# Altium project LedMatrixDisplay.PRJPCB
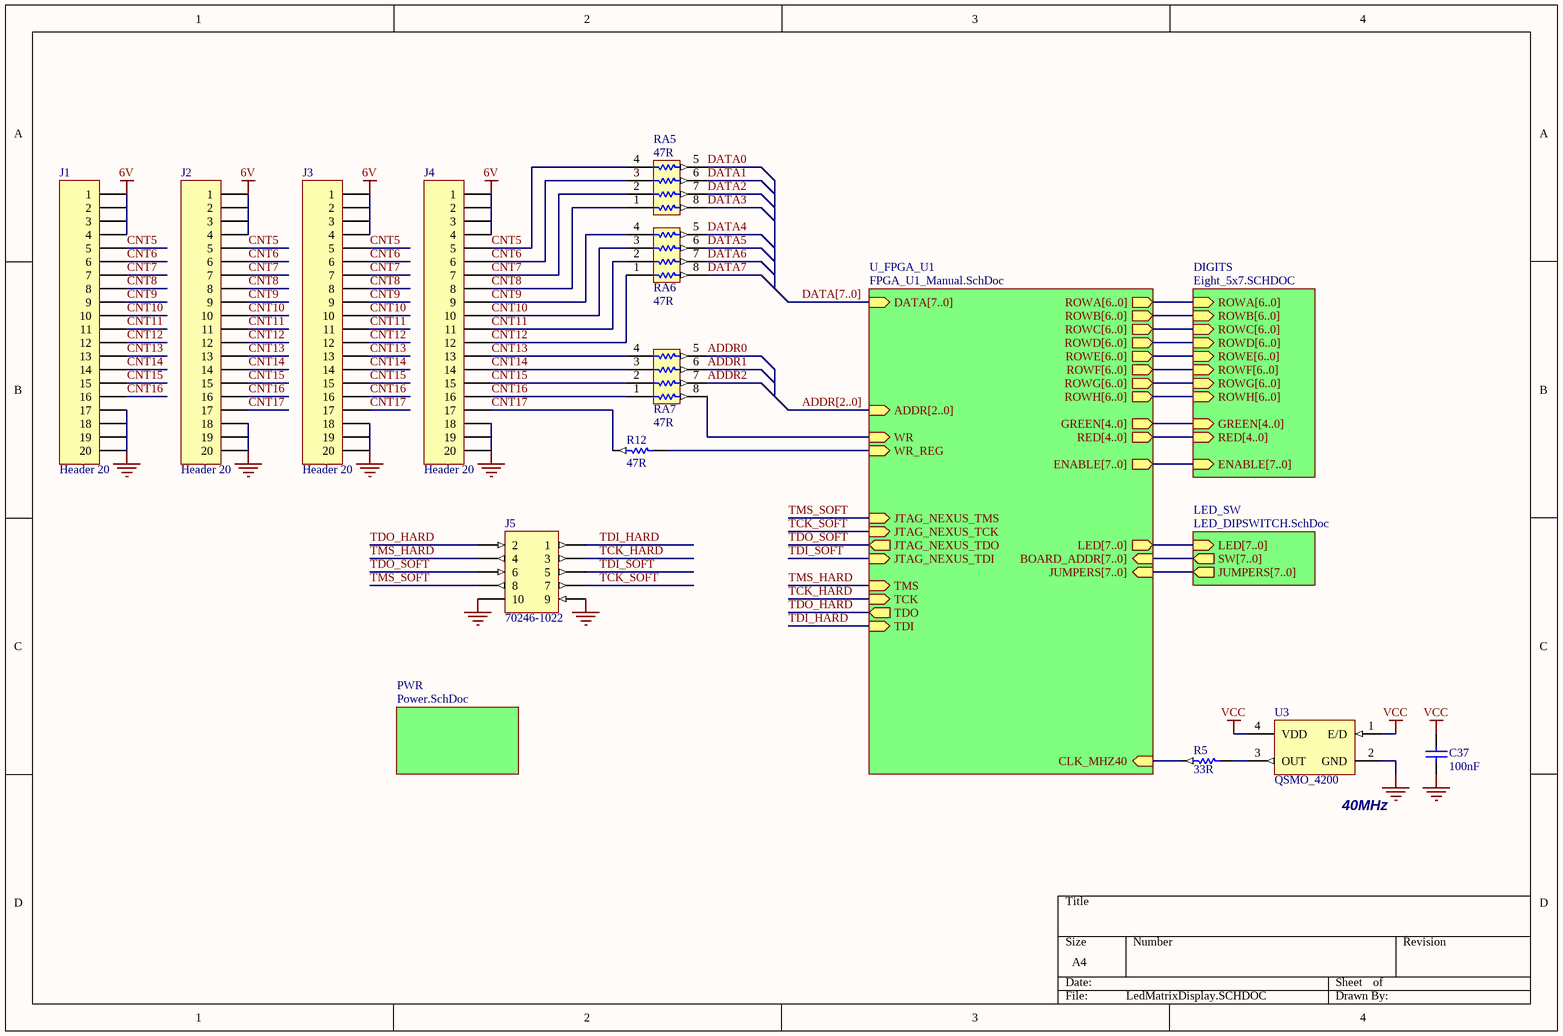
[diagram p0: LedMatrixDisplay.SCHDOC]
7 sheets, 103 parts. Net scope: hierarchical (ports join the sheet entries above them; power ports are global).
Board file: LedMatrixDisplay.PCBDOC
Sheets:
  LedMatrixDisplay.SCHDOC
    DIGITS = Eight_5x7.SCHDOC
      DG7 = DigitHolder.SCHDOC
      DG6 = DigitHolder.SCHDOC
      DG5 = DigitHolder.SCHDOC
      DG4 = DigitHolder.SCHDOC
      DG3 = DigitHolder.SCHDOC
      DG2 = DigitHolder.SCHDOC
      DG1 = DigitHolder.SCHDOC
      DG8 = DigitHolder.SCHDOC
    U_FPGA_U1 = FPGA_U1_Manual.SchDoc
      U_FPGA_U1_Auto = FPGA_U1_Auto.SchDoc
    PWR = Power.SchDoc
    LED_SW = LED_DIPSWITCH.SchDoc

## Sheet LedMatrixDisplay.SCHDOC
size A4; DocumentNumber: 1; SheetNumber: 1; SheetTotal: 7

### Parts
C37  100nF  [CC2012-0805]
J1  Header 20  [HDR2X10]
J2  Header 20  [HDR2X10]
J3  Header 20  [HDR2X10]
J4  Header 20  [HDR2X10]
J5  70246-1022  [HDR2X5_LP]
R5  33R  [CC2012-0805]
R12  47R  [CC2012-0805]
RA5  47R  [MNR34]
RA6  47R  [MNR34]
RA7  47R  [MNR34]
U3  QSMO_4200  [QSMO_4200]

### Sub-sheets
DIGITS = Eight_5x7.SCHDOC: ROWB[6..0] (in), ROWC[6..0] (in), ROWD[6..0] (in), ROWF[6..0] (in), ROWG[6..0] (in), ROWH[6..0] (in), ROWE[6..0] (in), ROWA[6..0] (in), GREEN[4..0] (in), RED[4..0] (in), ENABLE[7..0] (in)
LED_SW = LED_DIPSWITCH.SchDoc: LED[7..0] (in), SW[7..0] (out), JUMPERS[7..0] (out)
PWR = Power.SchDoc: no entries
U_FPGA_U1 = FPGA_U1_Manual.SchDoc: CLK_MHZ40 (in), DATA[7..0] (in), GREEN[4..0] (out), JTAG_NEXUS_TCK (in), JTAG_NEXUS_TDI (in), JTAG_NEXUS_TDO (out), JTAG_NEXUS_TMS (in), RED[4..0] (out), ADDR[2..0] (in), ROWA[6..0] (out), ROWB[6..0] (out), ROWC[6..0] (out), ROWD[6..0] (out), ROWE[6..0] (out), ROWF[6..0] (out), ROWG[6..0] (out), ROWH[6..0] (out), WR (in), TCK (in), TDI (in), TDO (out), TMS (in), BOARD_ADDR[7..0] (in), LED[7..0] (out), ENABLE[7..0] (out), JUMPERS[7..0] (in), WR_REG (in)

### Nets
6V: J1.1 J1.2 J1.3 J1.4 J2.1 J2.2 J2.3 J2.4 J3.1 J3.2 J3.3 J3.4 J4.1 J4.2 J4.3 J4.4
GND: C37.2 J1.17 J1.18 J1.19 J1.20 J2.18 J2.19 J2.20 J3.18 J3.19 J3.20 J4.18 J4.19 J4.20 J5.9 J5.10 U3.2(GND)
VCC: C37.1 U3.1(E/D) U3.4(VDD)  [project net VCCO]
ADDR0: RA7.5
ADDR1: RA7.6
ADDR2: RA7.7
CLK_MHZ40: R5.2 ; sheet U_FPGA_U1/CLK_MHZ40
CNT5: J1.5 J2.5 J3.5 J4.5 RA5.4
CNT6: J1.6 J2.6 J3.6 J4.6 RA5.3
CNT7: J1.7 J2.7 J3.7 J4.7 RA5.2
CNT8: J1.8 J2.8 J3.8 J4.8 RA5.1
CNT9: J1.9 J2.9 J3.9 J4.9 RA6.4
CNT10: J1.10 J2.10 J3.10 J4.10 RA6.3
CNT11: J1.11 J2.11 J3.11 J4.11 RA6.2
CNT12: J1.12 J2.12 J3.12 J4.12 RA6.1
CNT13: J1.13 J2.13 J3.13 J4.13 RA7.4
CNT14: J1.14 J2.14 J3.14 J4.14 RA7.3
CNT15: J1.15 J2.15 J3.15 J4.15 RA7.2
CNT16: J1.16 J2.16 J3.16 J4.16 RA7.1
CNT17: J2.17 J3.17 J4.17 R12.2
DATA0: RA5.5
DATA1: RA5.6
DATA2: RA5.7
DATA3: RA5.8
DATA4: RA6.5
DATA5: RA6.6
DATA6: RA6.7
DATA7: RA6.8
TCK_HARD: J5.3 ; sheet U_FPGA_U1/TCK
TCK_SOFT: J5.7 ; sheet U_FPGA_U1/JTAG_NEXUS_TCK
TDI_HARD: J5.1 ; sheet U_FPGA_U1/TDI
TDI_SOFT: J5.5 ; sheet U_FPGA_U1/JTAG_NEXUS_TDI
TDO_HARD: J5.2 ; sheet U_FPGA_U1/TDO
TDO_SOFT: J5.6 ; sheet U_FPGA_U1/JTAG_NEXUS_TDO
TMS_HARD: J5.4 ; sheet U_FPGA_U1/TMS
TMS_SOFT: J5.8 ; sheet U_FPGA_U1/JTAG_NEXUS_TMS
WR: RA7.8 ; sheet U_FPGA_U1/WR
WR_REG: R12.1 ; sheet U_FPGA_U1/WR_REG
NetR5_1: R5.1 U3.3(OUT)

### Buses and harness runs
bus ADDR[2..0] = sheet U_FPGA_U1/ADDR[2..0]
bus DATA[7..0] = sheet U_FPGA_U1/DATA[7..0]
bus sheet DIGITS/ENABLE[7..0] = sheet U_FPGA_U1/ENABLE[7..0]
bus sheet DIGITS/GREEN[4..0] = sheet U_FPGA_U1/GREEN[4..0]
bus sheet DIGITS/RED[4..0] = sheet U_FPGA_U1/RED[4..0]
bus sheet DIGITS/ROWA[6..0] = sheet U_FPGA_U1/ROWA[6..0]
bus sheet DIGITS/ROWB[6..0] = sheet U_FPGA_U1/ROWB[6..0]
bus sheet DIGITS/ROWC[6..0] = sheet U_FPGA_U1/ROWC[6..0]
bus sheet DIGITS/ROWD[6..0] = sheet U_FPGA_U1/ROWD[6..0]
bus sheet DIGITS/ROWE[6..0] = sheet U_FPGA_U1/ROWE[6..0]
bus sheet DIGITS/ROWF[6..0] = sheet U_FPGA_U1/ROWF[6..0]
bus sheet DIGITS/ROWG[6..0] = sheet U_FPGA_U1/ROWG[6..0]
bus sheet DIGITS/ROWH[6..0] = sheet U_FPGA_U1/ROWH[6..0]
bus sheet LED_SW/JUMPERS[7..0] = sheet U_FPGA_U1/JUMPERS[7..0]
bus sheet LED_SW/LED[7..0] = sheet U_FPGA_U1/LED[7..0]
bus sheet LED_SW/SW[7..0] = sheet U_FPGA_U1/BOARD_ADDR[7..0]

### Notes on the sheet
- (near U3) 40MHz

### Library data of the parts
C37 = CAP: Capacitor; Fitted: False
J1-J4 = Header 20: Header, 20-Pin; Manufacturer: Generic Components; Class I: Connector
J5 = Header 5X2: Header, 5-Pin, Dual row; Manufacturer: Molex; Class I: Connector; Fitted: True
R5 R12 = RES: Resistor; Fitted: False
RA5-RA7 = MNR34: 3216x4 Resistor Array; Fitted: True
U3 = QSMO_4200: Surface Mount Crystal Oscillator; Fitted: False

## Sheet Eight_5x7.SCHDOC
size A4 portrait; Organization: Altium Limited; Address1: L3, 12a Rodborough Rd; Address2: Frenchs Forest; Address3: NSW; Address4: Australia 2086; DocumentNumber: 2; SheetNumber: 2; SheetTotal: 7
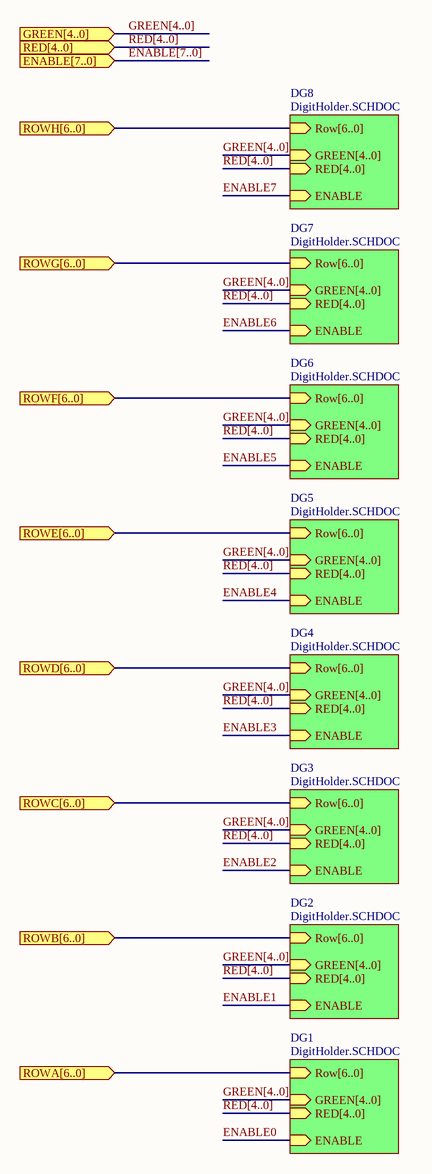
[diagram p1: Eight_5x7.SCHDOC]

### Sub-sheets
DG1 = DigitHolder.SCHDOC: Row[6..0] (in), ENABLE (in), GREEN[4..0] (in), RED[4..0] (in)
DG2 = DigitHolder.SCHDOC: Row[6..0] (in), ENABLE (in), GREEN[4..0] (in), RED[4..0] (in)
DG3 = DigitHolder.SCHDOC: Row[6..0] (in), ENABLE (in), GREEN[4..0] (in), RED[4..0] (in)
DG4 = DigitHolder.SCHDOC: Row[6..0] (in), ENABLE (in), GREEN[4..0] (in), RED[4..0] (in)
DG5 = DigitHolder.SCHDOC: Row[6..0] (in), ENABLE (in), GREEN[4..0] (in), RED[4..0] (in)
DG6 = DigitHolder.SCHDOC: Row[6..0] (in), ENABLE (in), GREEN[4..0] (in), RED[4..0] (in)
DG7 = DigitHolder.SCHDOC: Row[6..0] (in), ENABLE (in), GREEN[4..0] (in), RED[4..0] (in)
DG8 = DigitHolder.SCHDOC: Row[6..0] (in), ENABLE (in), GREEN[4..0] (in), RED[4..0] (in)

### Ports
ENABLE[7..0] (in), GREEN[4..0] (in), RED[4..0] (in), ROWA[6..0] (in), ROWB[6..0] (in), ROWC[6..0] (in), ROWD[6..0] (in), ROWE[6..0] (in), ROWF[6..0] (in), ROWG[6..0] (in), ROWH[6..0] (in)

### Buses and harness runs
bus ENABLE[7..0] = port ENABLE[7..0]
bus GREEN[4..0] = port GREEN[4..0]
bus GREEN[4..0] = sheet DG1/GREEN[4..0]
bus GREEN[4..0] = sheet DG2/GREEN[4..0]
bus GREEN[4..0] = sheet DG3/GREEN[4..0]
bus GREEN[4..0] = sheet DG4/GREEN[4..0]
bus GREEN[4..0] = sheet DG5/GREEN[4..0]
bus GREEN[4..0] = sheet DG6/GREEN[4..0]
bus GREEN[4..0] = sheet DG7/GREEN[4..0]
bus GREEN[4..0] = sheet DG8/GREEN[4..0]
bus port ROWA[6..0] = sheet DG1/Row[6..0]
bus port ROWB[6..0] = sheet DG2/Row[6..0]
bus port ROWC[6..0] = sheet DG3/Row[6..0]
bus port ROWD[6..0] = sheet DG4/Row[6..0]
bus port ROWE[6..0] = sheet DG5/Row[6..0]
bus port ROWF[6..0] = sheet DG6/Row[6..0]
bus port ROWG[6..0] = sheet DG7/Row[6..0]
bus port ROWH[6..0] = sheet DG8/Row[6..0]
bus RED[4..0] = port RED[4..0]
bus RED[4..0] = sheet DG1/RED[4..0]
bus RED[4..0] = sheet DG2/RED[4..0]
bus RED[4..0] = sheet DG3/RED[4..0]
bus RED[4..0] = sheet DG4/RED[4..0]
bus RED[4..0] = sheet DG5/RED[4..0]
bus RED[4..0] = sheet DG6/RED[4..0]
bus RED[4..0] = sheet DG7/RED[4..0]
bus RED[4..0] = sheet DG8/RED[4..0]

## Sheet DigitHolder.SCHDOC
size A4; DocumentNumber: 6; SheetNumber: 6; SheetTotal: 7
Used 8 times, as channels DIGITS/DG7, DIGITS/DG6, DIGITS/DG5, DIGITS/DG4, DIGITS/DG3, DIGITS/DG2, DIGITS/DG1, DIGITS/DG8. Parts and nets are listed once, with the designators drawn on the sheet.
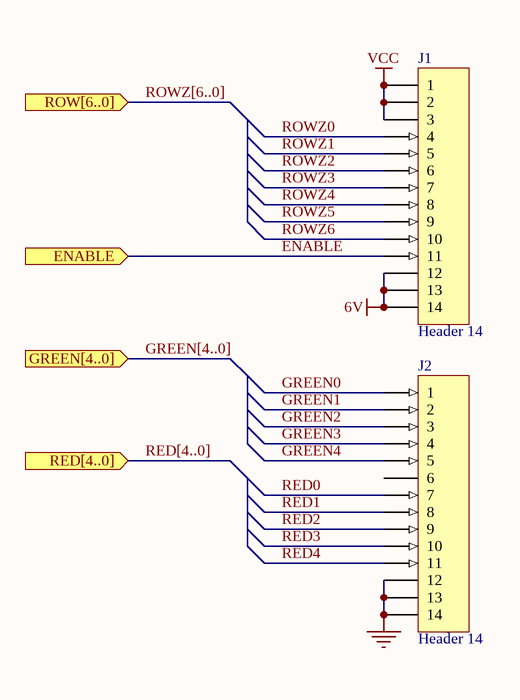
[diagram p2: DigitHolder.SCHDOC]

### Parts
J1  Header 14  [HDR1X14]
J2  Header 14  [HDR1X14]

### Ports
ENABLE (in), GREEN[4..0] (in), RED[4..0] (in), ROW[6..0] (in)

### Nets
6V: J1.12 J1.13 J1.14
GND: J2.12 J2.13 J2.14
VCC: J1.1 J1.2 J1.3
ENABLE: J1.11 ; port ENABLE
GREEN0: J2.1
GREEN1: J2.2
GREEN2: J2.3
GREEN3: J2.4
GREEN4: J2.5
RED0: J2.7
RED1: J2.8
RED2: J2.9
RED3: J2.10
RED4: J2.11
ROWZ0: J1.4
ROWZ1: J1.5
ROWZ2: J1.6
ROWZ3: J1.7
ROWZ4: J1.8
ROWZ5: J1.9
ROWZ6: J1.10

Not connected (* = marked no-connect by the designer): J2 6

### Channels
DIGITS/DG7: designators end in _DG7; ports ENABLE=ENABLE6
DIGITS/DG6: designators end in _DG6; ports ENABLE=ENABLE5
DIGITS/DG5: designators end in _DG5; ports ENABLE=ENABLE4
DIGITS/DG4: designators end in _DG4; ports ENABLE=ENABLE3
DIGITS/DG3: designators end in _DG3; ports ENABLE=ENABLE2
DIGITS/DG2: designators end in _DG2; ports ENABLE=ENABLE1
DIGITS/DG1: designators end in _DG1; ports ENABLE=ENABLE0
DIGITS/DG8: designators end in _DG8; ports ENABLE=ENABLE7

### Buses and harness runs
bus GREEN[4..0] = port GREEN[4..0]
bus RED[4..0] = port RED[4..0]
bus ROWZ[6..0] = port ROW[6..0]

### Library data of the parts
J1 J2 = Header 14: Header, 14-Pin; Manufacturer: Generic Components; Class I: Connector

## Sheet FPGA_U1_Manual.SchDoc
size A4; DocumentNumber: 4; SheetNumber: 4; SheetTotal: 7
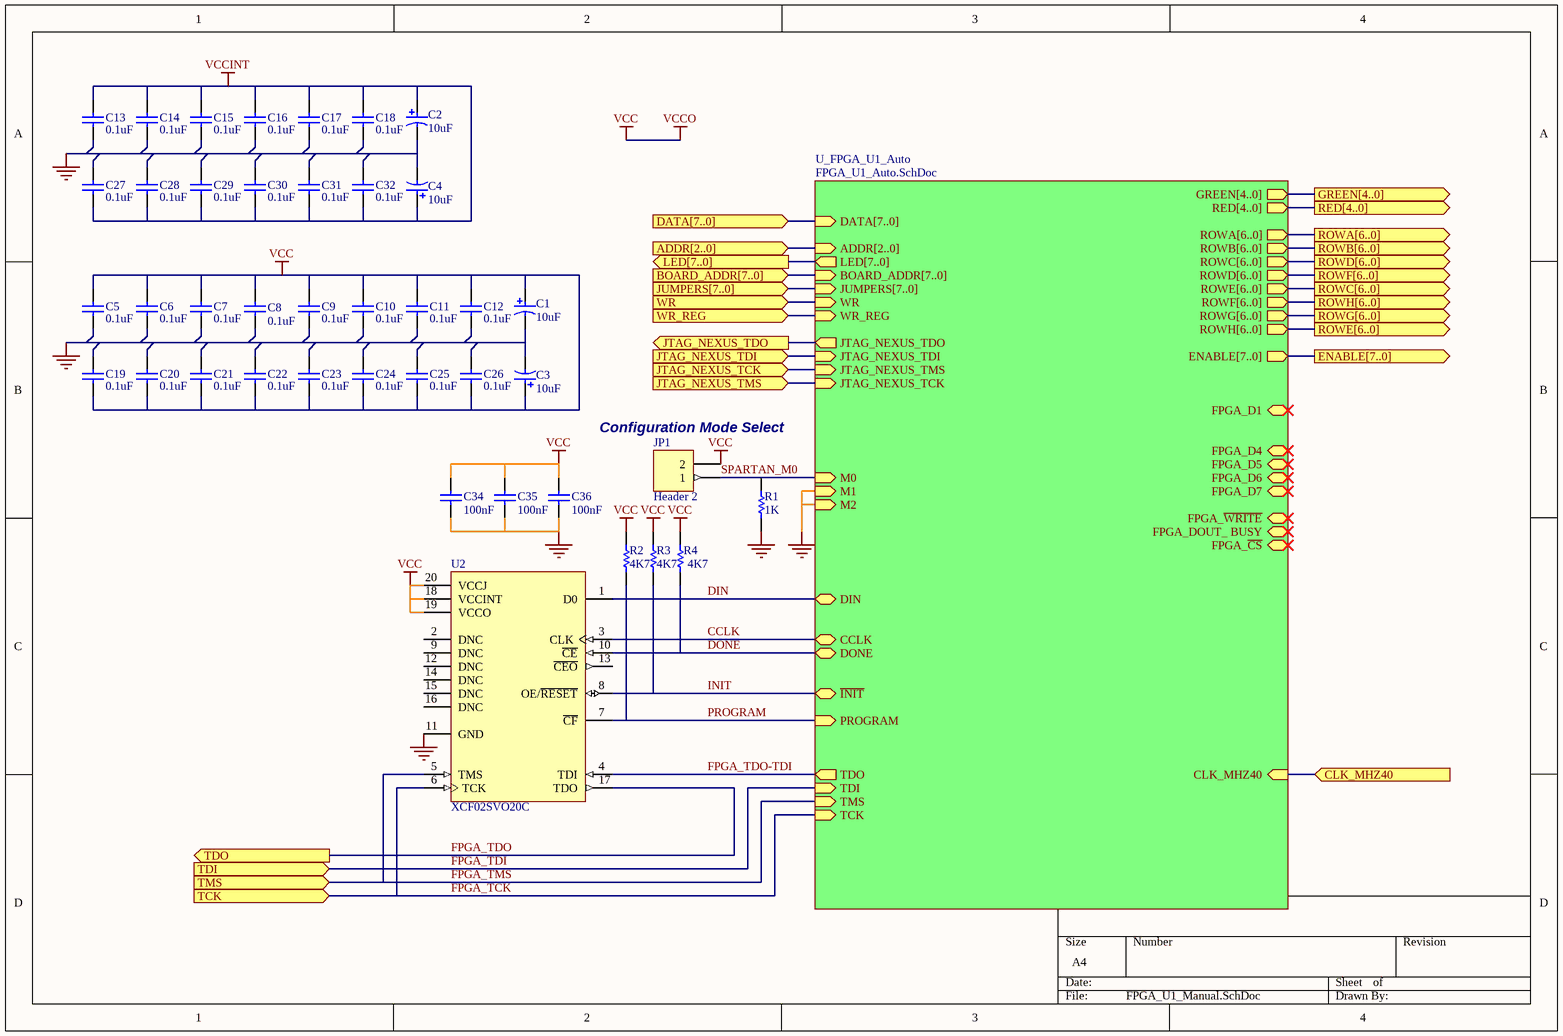
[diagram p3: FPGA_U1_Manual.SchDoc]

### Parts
C1  10uF  [MCCT-B]
C2  10uF  [MCCT-B]
C3  10uF  [MCCT-B]
C4  10uF  [MCCT-B]
C5  0.1uF  [CC2012-0805]
C6  0.1uF  [CC2012-0805]
C7  0.1uF  [CC2012-0805]
C8  0.1uF  [CC2012-0805]
C9  0.1uF  [CC2012-0805]
C10  0.1uF  [CC2012-0805]
C11  0.1uF  [CC2012-0805]
C12  0.1uF  [CC2012-0805]
C13  0.1uF  [CC2012-0805]
C14  0.1uF  [CC2012-0805]
C15  0.1uF  [CC2012-0805]
C16  0.1uF  [CC2012-0805]
C17  0.1uF  [CC2012-0805]
C18  0.1uF  [CC2012-0805]
C19  0.1uF  [CC2012-0805]
C20  0.1uF  [CC2012-0805]
C21  0.1uF  [CC2012-0805]
C22  0.1uF  [CC2012-0805]
C23  0.1uF  [CC2012-0805]
C24  0.1uF  [CC2012-0805]
C25  0.1uF  [CC2012-0805]
C26  0.1uF  [CC2012-0805]
C27  0.1uF  [CC2012-0805]
C28  0.1uF  [CC2012-0805]
C29  0.1uF  [CC2012-0805]
C30  0.1uF  [CC2012-0805]
C31  0.1uF  [CC2012-0805]
C32  0.1uF  [CC2012-0805]
C34  100nF  [CC2012-0805]
C35  100nF  [CC2012-0805]
C36  100nF  [CC2012-0805]
JP1  Header 2  Usage: Configuration Mode Select  [HDR1X2]
R1  1K  [CC2012-0805]
R2  4K7  [CC2012-0805]
R3  4K7  [CC2012-0805]
R4  4K7  [CC2012-0805]
U2  XCF02SVO20C  [VO20]

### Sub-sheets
U_FPGA_U1_Auto = FPGA_U1_Auto.SchDoc: ADDR[2..0] (in), BOARD_ADDR[7..0] (in), CLK_MHZ40 (in), DATA[7..0] (in), GREEN[4..0] (out), JTAG_NEXUS_TCK (in), JTAG_NEXUS_TDI (in), JTAG_NEXUS_TDO (out), JTAG_NEXUS_TMS (in), LED[7..0] (out), RED[4..0] (out), ROWA[6..0] (out), ROWB[6..0] (out), ROWC[6..0] (out), ROWD[6..0] (out), ROWE[6..0] (out), ROWF[6..0] (out), ROWG[6..0] (out), ROWH[6..0] (out), WR (in), CCLK (bidir), DONE (bidir), FPGA_D7 (bidir), M0 (in), M1 (in), M2 (in), PROGRAM (in), TCK (in), TDI (in), TDO (out), TMS (in), FPGA_DOUT_ BUSY (bidir), FPGA_~{WRITE} (bidir), FPGA_D5 (bidir), FPGA_D6 (bidir), FPGA_~{CS} (bidir), FPGA_D1 (bidir), FPGA_D4 (bidir), ENABLE[7..0] (out), JUMPERS[7..0] (in), DIN (bidir), ~{INIT} (bidir), WR_REG (in)

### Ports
ADDR[2..0] (in), BOARD_ADDR[7..0] (in), CLK_MHZ40 (in), DATA[7..0] (in), ENABLE[7..0] (out), GREEN[4..0] (out), JTAG_NEXUS_TCK (in), JTAG_NEXUS_TDI (in), JTAG_NEXUS_TDO (out), JTAG_NEXUS_TMS (in), JUMPERS[7..0] (in), LED[7..0] (out), RED[4..0] (out), ROWA[6..0] (out), ROWB[6..0] (out), ROWC[6..0] (out), ROWD[6..0] (out), ROWE[6..0] (out), ROWF[6..0] (out), ROWG[6..0] (out), ROWH[6..0] (out), TCK (in), TDI (in), TDO (out), TMS (in), WR (in), WR_REG (in)

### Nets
GND: C1.2 C2.2 C3.2 C4.2 C5.1 C6.1 C7.1 C8.1 C9.1 C10.1 C11.1 C12.1 C13.1 C14.1 C15.1 C16.1 C17.1 C18.1 C19.2 C20.2 C21.2 C22.2 C23.2 C24.2 C25.2 C26.2 C27.2 C28.2 C29.2 C30.2 C31.2 C32.2 C34.1 C35.1 C36.1 R1.1 U2.11(GND) ; sheet U_FPGA_U1_Auto/M1, sheet U_FPGA_U1_Auto/M2
VCCINT: C2.1 C4.1 C13.2 C14.2 C15.2 C16.2 C17.2 C18.2 C27.1 C28.1 C29.1 C30.1 C31.1 C32.1
VCCO: C1.1 C3.1 C5.2 C6.2 C7.2 C8.2 C9.2 C10.2 C11.2 C12.2 C19.1 C20.1 C21.1 C22.1 C23.1 C24.1 C25.1 C26.1 C34.2 C35.2 C36.2 JP1.2 R2.1 R3.1 R4.1 U2.18(VCCINT) U2.19(VCCO) U2.20(VCCJ)  [also labelled VCC]
CCLK: U2.3(CLK) ; sheet U_FPGA_U1_Auto/CCLK
CLK_MHZ40: port CLK_MHZ40, sheet U_FPGA_U1_Auto/CLK_MHZ40
DIN: U2.1(D0) ; sheet U_FPGA_U1_Auto/DIN
DONE: R4.2 U2.10(~{CE}) ; sheet U_FPGA_U1_Auto/DONE
FPGA_TCK: U2.6(TCK) ; port TCK, sheet U_FPGA_U1_Auto/TCK  [project net TCK_HARD]
FPGA_TDI: port TDI, sheet U_FPGA_U1_Auto/TDI  [project net TDI_HARD]
FPGA_TDO: U2.17(TDO) ; port TDO  [project net TDO_HARD]
FPGA_TDO-TDI: U2.4(TDI) ; sheet U_FPGA_U1_Auto/TDO
FPGA_TMS: U2.5(TMS) ; port TMS, sheet U_FPGA_U1_Auto/TMS  [project net TMS_HARD]
INIT: R3.2 U2.8(OE/~{RESET}) ; sheet U_FPGA_U1_Auto/~{INIT}
PROGRAM: R2.2 U2.7(~{CF}) ; sheet U_FPGA_U1_Auto/PROGRAM
SPARTAN_M0: JP1.1 R1.2 ; sheet U_FPGA_U1_Auto/M0
TCK_SOFT: port JTAG_NEXUS_TCK, sheet U_FPGA_U1_Auto/JTAG_NEXUS_TMS
TDI_SOFT: port JTAG_NEXUS_TDI, sheet U_FPGA_U1_Auto/JTAG_NEXUS_TDI
TDO_SOFT: port JTAG_NEXUS_TDO, sheet U_FPGA_U1_Auto/JTAG_NEXUS_TDO
TMS_SOFT: port JTAG_NEXUS_TMS, sheet U_FPGA_U1_Auto/JTAG_NEXUS_TCK
WR: port WR, sheet U_FPGA_U1_Auto/WR
WR_REG: port WR_REG, sheet U_FPGA_U1_Auto/WR_REG

Not connected (* = marked no-connect by the designer): U2 2(DNC) 9(DNC) 12(DNC) 13(~{CEO}) 14(DNC) 15(DNC) 16(DNC)

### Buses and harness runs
bus port ADDR[2..0] = sheet U_FPGA_U1_Auto/ADDR[2..0]
bus port BOARD_ADDR[7..0] = sheet U_FPGA_U1_Auto/BOARD_ADDR[7..0]
bus port DATA[7..0] = sheet U_FPGA_U1_Auto/DATA[7..0]
bus port ENABLE[7..0] = sheet U_FPGA_U1_Auto/ENABLE[7..0]
bus port GREEN[4..0] = sheet U_FPGA_U1_Auto/GREEN[4..0]
bus port JUMPERS[7..0] = sheet U_FPGA_U1_Auto/JUMPERS[7..0]
bus port LED[7..0] = sheet U_FPGA_U1_Auto/LED[7..0]
bus port RED[4..0] = sheet U_FPGA_U1_Auto/RED[4..0]
bus port ROWA[6..0] = sheet U_FPGA_U1_Auto/ROWA[6..0]
bus port ROWB[6..0] = sheet U_FPGA_U1_Auto/ROWB[6..0]
bus port ROWC[6..0] = sheet U_FPGA_U1_Auto/ROWE[6..0]
bus port ROWD[6..0] = sheet U_FPGA_U1_Auto/ROWC[6..0]
bus port ROWE[6..0] = sheet U_FPGA_U1_Auto/ROWH[6..0]
bus port ROWF[6..0] = sheet U_FPGA_U1_Auto/ROWD[6..0]
bus port ROWG[6..0] = sheet U_FPGA_U1_Auto/ROWG[6..0]
bus port ROWH[6..0] = sheet U_FPGA_U1_Auto/ROWF[6..0]

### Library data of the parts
C1-C4 = CAP_POLAR: Polar Capacitor
C5-C32 = CAP: Capacitor
C34-C36 = CAP: Capacitor; Fitted: True
JP1 = Header 2: Header, 2-Pin; Manufacturer: Generic Components; Class I: Connector; Fitted: True
R1-R4 = RES: Resistor; Fitted: True
U2 = XCF02SVO20C: XCF00S Series, Platform Flash In-System Programmable Configuration 3.3V PROM, 20-Pin TSOP, 2-Megabit, Commercial Grade; Manufacturer: Xilinx; Package Information: Latest Revision: ver1.0, May-2003; Code - JEDEC: MO-153-AC

## Sheet FPGA_U1_Auto.SchDoc
size A2; DocumentNumber: 7; SheetNumber: 7; SheetTotal: 7; Generated From FPGA Project: LedMatrix.PrjFpg; UNUSED_SPECIAL: RouteSeparate; UNUSED_IO: NoERC; VREF: NoERC; UNUSED_INPUT: NoERC
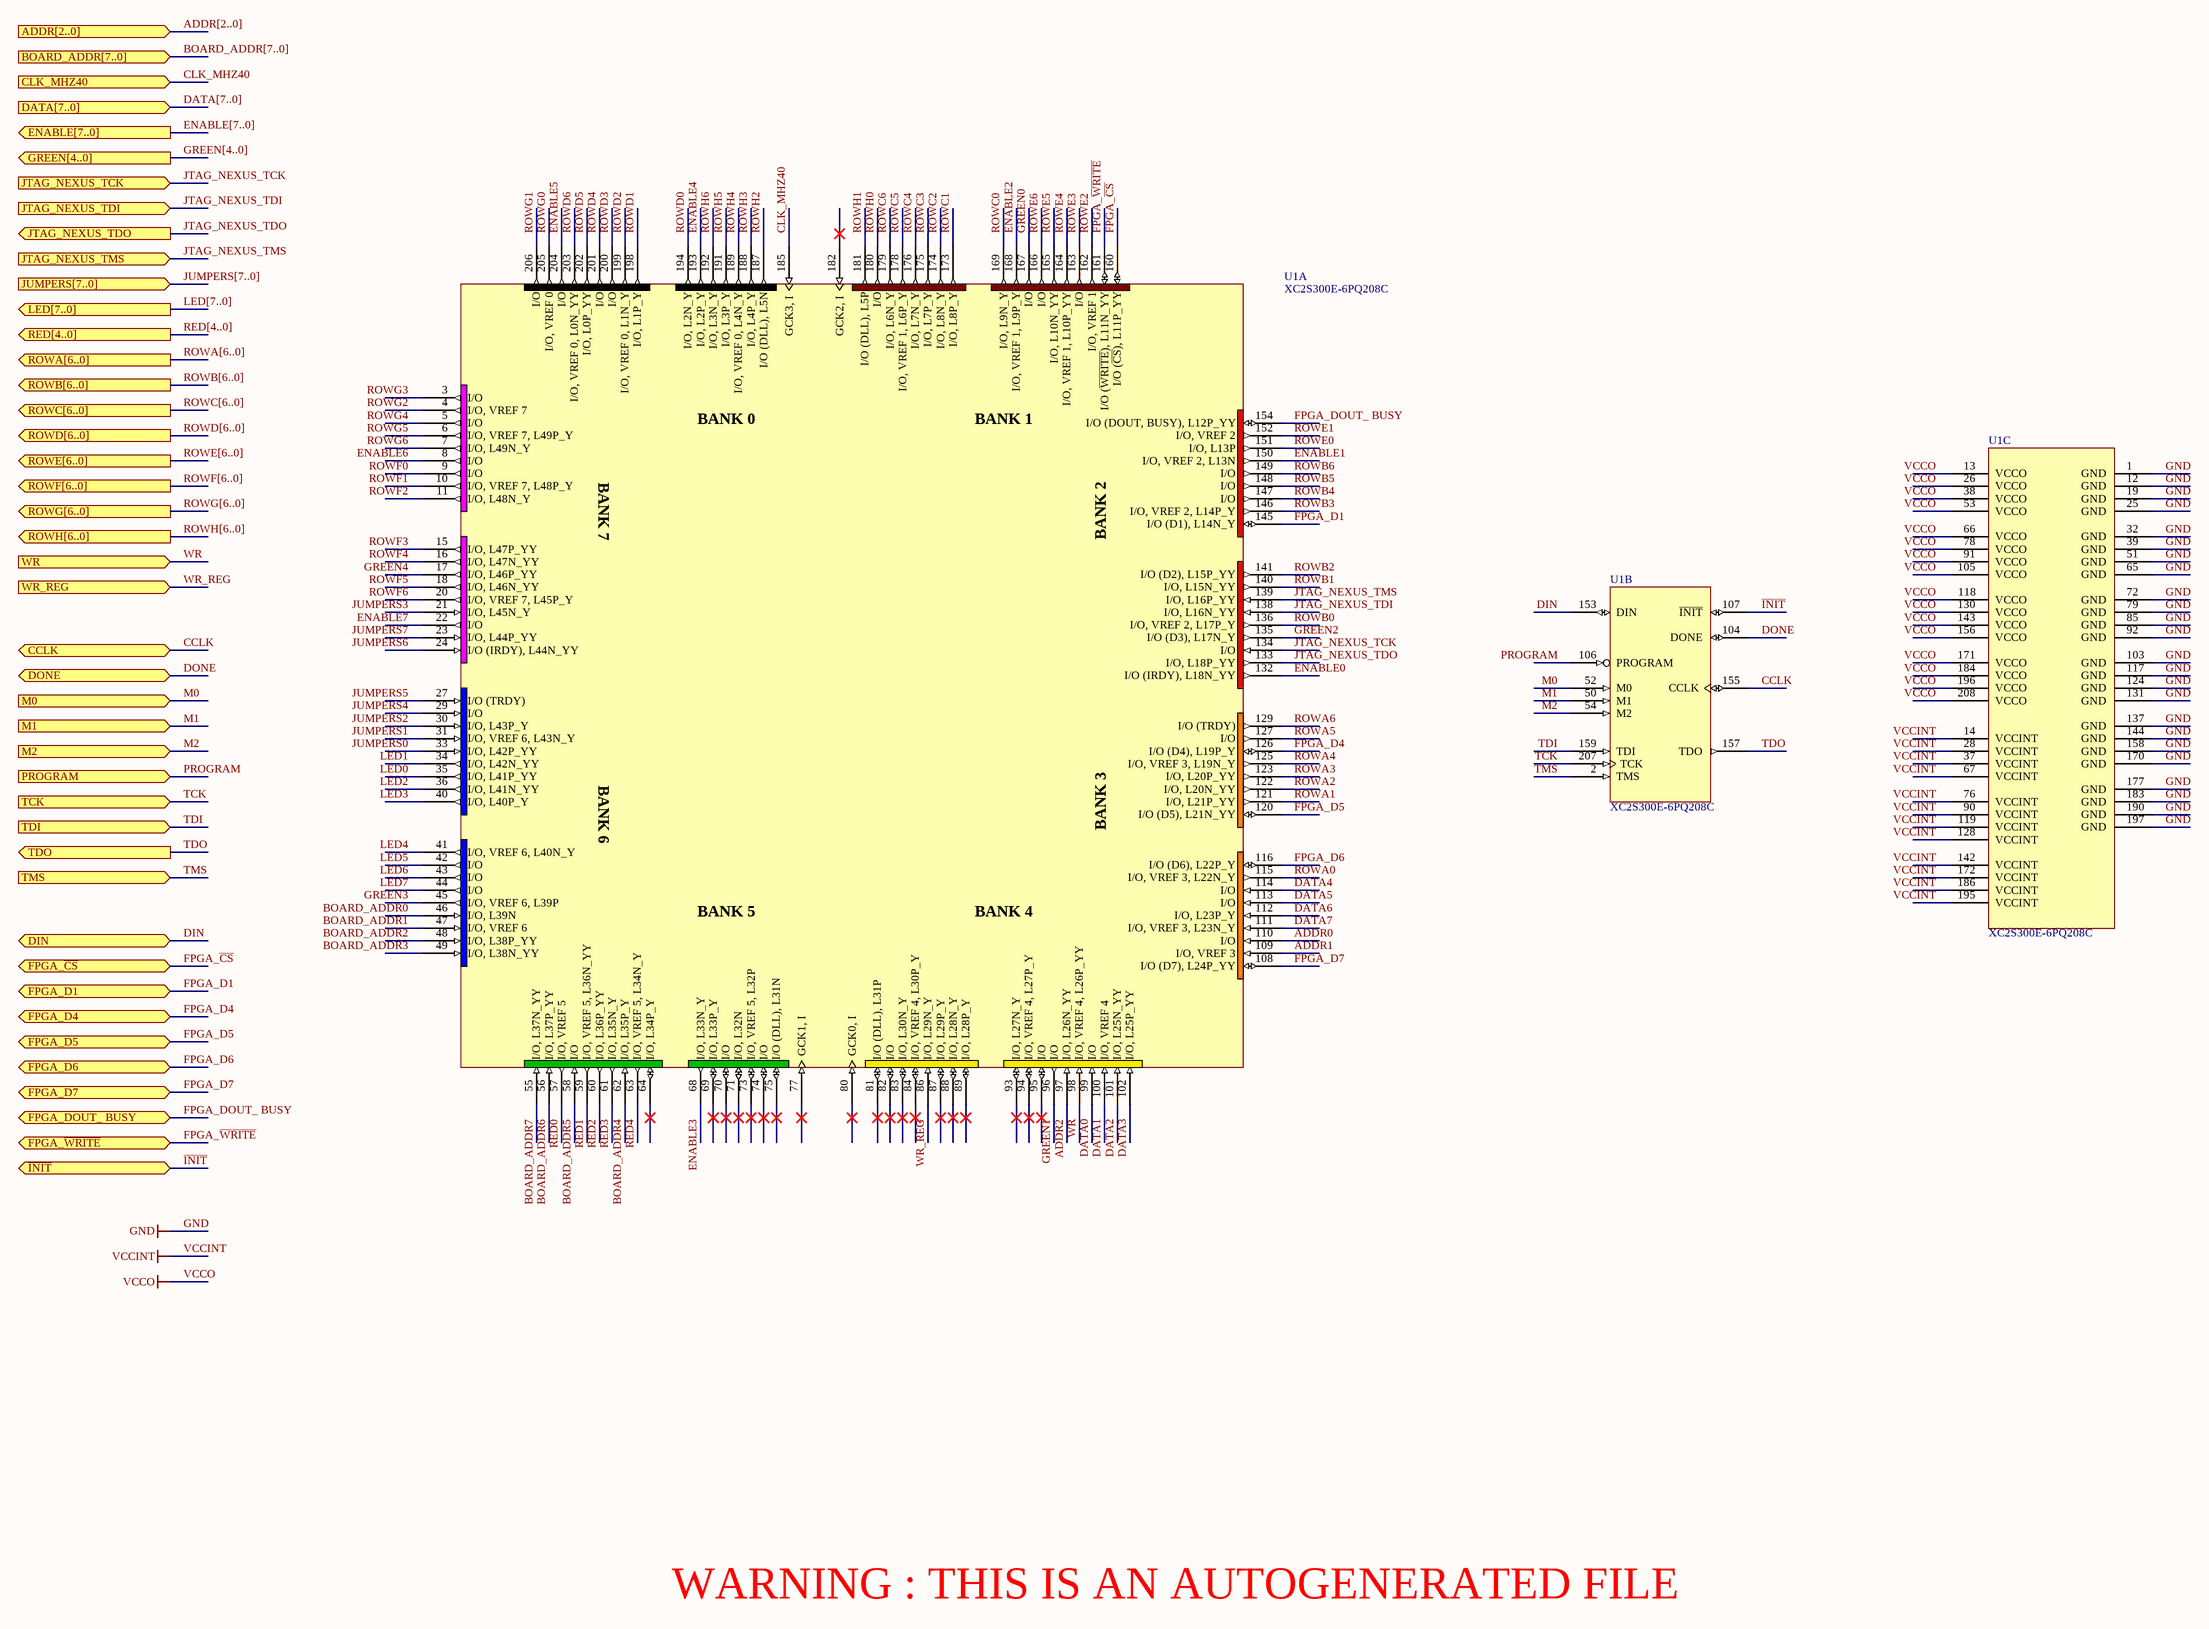
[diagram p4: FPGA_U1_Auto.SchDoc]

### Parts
U1  XC2S300E-6PQ208C  [PQ208]  (parts A,B,C of 3)

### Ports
ADDR[2..0] (in), BOARD_ADDR[7..0] (in), CCLK (bidir), CLK_MHZ40 (in), DATA[7..0] (in), DIN (bidir), DONE (bidir), ENABLE[7..0] (out), FPGA_D1 (bidir), FPGA_D4 (bidir), FPGA_D5 (bidir), FPGA_D6 (bidir), FPGA_D7 (bidir), FPGA_DOUT_ BUSY (bidir), FPGA_~{CS} (bidir), FPGA_~{WRITE} (bidir), GREEN[4..0] (out), JTAG_NEXUS_TCK (in), JTAG_NEXUS_TDI (in), JTAG_NEXUS_TDO (out), JTAG_NEXUS_TMS (in), JUMPERS[7..0] (in), LED[7..0] (out), M0 (in), M1 (in), M2 (in), PROGRAM (in), RED[4..0] (out), ROWA[6..0] (out), ROWB[6..0] (out), ROWC[6..0] (out), ROWD[6..0] (out), ROWE[6..0] (out), ROWF[6..0] (out), ROWG[6..0] (out), ROWH[6..0] (out), TCK (in), TDI (in), TDO (out), TMS (in), WR (in), WR_REG (in), ~{INIT} (bidir)

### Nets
GND: U1.1(GND) U1.12(GND) U1.19(GND) U1.25(GND) U1.32(GND) U1.39(GND) U1.50(M1) U1.51(GND) U1.54(M2) U1.65(GND) U1.72(GND) U1.79(GND) U1.85(GND) U1.92(GND) U1.103(GND) U1.117(GND) U1.124(GND) U1.131(GND) U1.137(GND) U1.144(GND) U1.158(GND) U1.170(GND) U1.177(GND) U1.183(GND) U1.190(GND) U1.197(GND) ; port M1, port M2  [also labelled M1, M2]
VCCINT: U1.14(VCCINT) U1.28(VCCINT) U1.37(VCCINT) U1.67(VCCINT) U1.76(VCCINT) U1.90(VCCINT) U1.119(VCCINT) U1.128(VCCINT) U1.142(VCCINT) U1.172(VCCINT) U1.186(VCCINT) U1.195(VCCINT)
VCCO: U1.13(VCCO) U1.26(VCCO) U1.38(VCCO) U1.53(VCCO) U1.66(VCCO) U1.78(VCCO) U1.91(VCCO) U1.105(VCCO) U1.118(VCCO) U1.130(VCCO) U1.143(VCCO) U1.156(VCCO) U1.171(VCCO) U1.184(VCCO) U1.196(VCCO) U1.208(VCCO)
ADDR0: U1.110(I/O)
ADDR1: U1.109(I/O,_VREF_3)
ADDR2: U1.97(I/O,_L26N_YY)
BOARD_ADDR0: U1.46(I/O,_L39N)  [project net SW0]
BOARD_ADDR1: U1.47(I/O,_VREF_6)  [project net SW1]
BOARD_ADDR2: U1.48(I/O,_L38P_YY)  [project net SW2]
BOARD_ADDR3: U1.49(I/O,_L38N_YY)  [project net SW3]
BOARD_ADDR4: U1.62(I/O,_L35P_Y)  [project net SW4]
BOARD_ADDR5: U1.58(I/O)  [project net SW5]
BOARD_ADDR6: U1.56(I/O,_L37P_YY)  [project net SW6]
BOARD_ADDR7: U1.55(I/O,_L37N_YY)  [project net SW7]
CCLK: U1.155(CCLK) ; port CCLK
CLK_MHZ40: U1.185(GCK3,_I) ; port CLK_MHZ40
DATA0: U1.99(I/O)
DATA1: U1.100(I/O,_VREF_4)
DATA2: U1.101(I/O,_L25N_YY)
DATA3: U1.102(I/O,_L25P_YY)
DATA4: U1.114(I/O)
DATA5: U1.113(I/O)
DATA6: U1.112(I/O,_L23P_Y)
DATA7: U1.111(I/O,_VREF_3,_L23N_Y)
DIN: U1.153(DIN) ; port DIN
DONE: U1.104(DONE) ; port DONE
ENABLE0: U1.132(I/O_(IRDY),_L18N_YY)
ENABLE1: U1.150(I/O,_VREF_2,_L13N)
ENABLE2: U1.168(I/O,_VREF_1,_L9P_Y)
ENABLE3: U1.68(I/O,_L33N_Y)
ENABLE4: U1.193(I/O,_L2P_Y)
ENABLE5: U1.204(I/O)
ENABLE6: U1.8(I/O)
ENABLE7: U1.22(I/O)
FPGA_~{CS}: U1.160(I/O_(~{CS}),_L11P_YY) ; port FPGA_~{CS}
FPGA_D1: U1.145(I/O_(D1),_L14N_Y) ; port FPGA_D1
FPGA_D4: U1.126(I/O_(D4),_L19P_Y) ; port FPGA_D4
FPGA_D5: U1.120(I/O_(D5),_L21N_YY) ; port FPGA_D5
FPGA_D6: U1.116(I/O_(D6),_L22P_Y) ; port FPGA_D6
FPGA_D7: U1.108(I/O_(D7),_L24P_YY) ; port FPGA_D7
FPGA_DOUT_ BUSY: U1.154(I/O_(DOUT,_BUSY),_L12P_YY) ; port FPGA_DOUT_ BUSY
FPGA_~{WRITE}: U1.161(I/O_(~{WRITE}),_L11N_YY) ; port FPGA_~{WRITE}
GREEN0: U1.167(I/O)
GREEN1: U1.96(I/O)
GREEN2: U1.135(I/O_(D3),_L17N_Y)
GREEN3: U1.45(I/O,_VREF_6,_L39P)
GREEN4: U1.17(I/O,_L46P_YY)
~{INIT}: U1.107(~{INIT}) ; port ~{INIT}  [project net INIT]
JTAG_NEXUS_TCK: U1.134(I/O) ; port JTAG_NEXUS_TCK  [project net TMS_SOFT]
JTAG_NEXUS_TDI: U1.138(I/O,_L16N_YY) ; port JTAG_NEXUS_TDI  [project net TDI_SOFT]
JTAG_NEXUS_TDO: U1.133(I/O,_L18P_YY) ; port JTAG_NEXUS_TDO  [project net TDO_SOFT]
JTAG_NEXUS_TMS: U1.139(I/O,_L16P_YY) ; port JTAG_NEXUS_TMS  [project net TCK_SOFT]
JUMPERS0: U1.33(I/O,_L42P_YY)
JUMPERS1: U1.31(I/O,_VREF_6,_L43N_Y)
JUMPERS2: U1.30(I/O,_L43P_Y)
JUMPERS3: U1.21(I/O,_L45N_Y)
JUMPERS4: U1.29(I/O)
JUMPERS5: U1.27(I/O_(TRDY))
JUMPERS6: U1.24(I/O_(IRDY),_L44N_YY)
JUMPERS7: U1.23(I/O,_L44P_YY)
LED0: U1.35(I/O,_L41P_YY)
LED1: U1.34(I/O,_L42N_YY)
LED2: U1.36(I/O,_L41N_YY)
LED3: U1.40(I/O,_L40P_Y)
LED4: U1.41(I/O,_VREF_6,_L40N_Y)
LED5: U1.42(I/O)
LED6: U1.43(I/O)
LED7: U1.44(I/O)
M0: U1.52(M0) ; port M0  [project net SPARTAN_M0]
PROGRAM: U1.106(PROGRAM) ; port PROGRAM
RED0: U1.57(I/O,_VREF_5)
RED1: U1.59(I/O,_VREF_5,_L36N_YY)
RED2: U1.60(I/O,_L36P_YY)
RED3: U1.61(I/O,_L35N_Y)
RED4: U1.63(I/O,_VREF_5,_L34N_Y)
ROWA0: U1.115(I/O,_VREF_3,_L22N_Y)
ROWA1: U1.121(I/O,_L21P_YY)
ROWA2: U1.122(I/O,_L20N_YY)
ROWA3: U1.123(I/O,_L20P_YY)
ROWA4: U1.125(I/O,_VREF_3,_L19N_Y)
ROWA5: U1.127(I/O)
ROWA6: U1.129(I/O_(TRDY))
ROWB0: U1.136(I/O,_VREF_2,_L17P_Y)
ROWB1: U1.140(I/O,_L15N_YY)
ROWB2: U1.141(I/O_(D2),_L15P_YY)
ROWB3: U1.146(I/O,_VREF_2,_L14P_Y)
ROWB4: U1.147(I/O)
ROWB5: U1.148(I/O)
ROWB6: U1.149(I/O)
ROWC0: U1.169(I/O,_L9N_Y)
ROWC1: U1.173(I/O,_L8P_Y)
ROWC2: U1.174(I/O,_L8N_Y)
ROWC3: U1.175(I/O,_L7P_Y)
ROWC4: U1.176(I/O,_L7N_Y)
ROWC5: U1.178(I/O,_VREF_1,_L6P_Y)
ROWC6: U1.179(I/O,_L6N_Y)
ROWD0: U1.194(I/O,_L2N_Y)
ROWD1: U1.198(I/O,_L1P_Y)
ROWD2: U1.199(I/O,_VREF_0,_L1N_Y)
ROWD3: U1.200(I/O)
ROWD4: U1.201(I/O)
ROWD5: U1.202(I/O,_L0P_YY)
ROWD6: U1.203(I/O,_VREF_0,_L0N_YY)
ROWE0: U1.151(I/O,_L13P)
ROWE1: U1.152(I/O,_VREF_2)
ROWE2: U1.162(I/O,_VREF_1)
ROWE3: U1.163(I/O)
ROWE4: U1.164(I/O,_VREF_1,_L10P_YY)
ROWE5: U1.165(I/O,_L10N_YY)
ROWE6: U1.166(I/O)
ROWF0: U1.9(I/O)
ROWF1: U1.10(I/O,_VREF_7,_L48P_Y)
ROWF2: U1.11(I/O,_L48N_Y)
ROWF3: U1.15(I/O,_L47P_YY)
ROWF4: U1.16(I/O,_L47N_YY)
ROWF5: U1.18(I/O,_L46N_YY)
ROWF6: U1.20(I/O,_VREF_7,_L45P_Y)
ROWG0: U1.205(I/O,_VREF_0)
ROWG1: U1.206(I/O)
ROWG2: U1.4(I/O,_VREF_7)
ROWG3: U1.3(I/O)
ROWG4: U1.5(I/O)
ROWG5: U1.6(I/O,_VREF_7,_L49P_Y)
ROWG6: U1.7(I/O,_L49N_Y)
ROWH0: U1.180(I/O)
ROWH1: U1.181(I/O_(DLL),_L5P)
ROWH2: U1.187(I/O_(DLL),_L5N)
ROWH3: U1.188(I/O,_L4P_Y)
ROWH4: U1.189(I/O,_VREF_0,_L4N_Y)
ROWH5: U1.191(I/O,_L3P_Y)
ROWH6: U1.192(I/O,_L3N_Y)
TCK: U1.207(TCK) ; port TCK  [project net TCK_HARD]
TDI: U1.159(TDI) ; port TDI  [project net TDI_HARD]
TDO: U1.157(TDO) ; port TDO  [project net FPGA_TDO-TDI]
TMS: U1.2(TMS) ; port TMS  [project net TMS_HARD]
WR: U1.98(I/O,_VREF_4,_L26P_YY) ; port WR
WR_REG: U1.86(I/O,_L29N_Y) ; port WR_REG

Not connected (* = marked no-connect by the designer): U1 64(I/O,_L34P_Y)* 69(I/O,_L33P_Y)* 70(I/O)* 71(I/O,_L32N)* 73(I/O,_VREF_5,_L32P)* 74(I/O)* 75(I/O_(DLL),_L31N)* 77(GCK1,_I)* 80(GCK0,_I)* 81(I/O_(DLL),_L31P)* 82(I/O)* 83(I/O,_L30N_Y)* 84(I/O,_VREF_4,_L30P_Y)* 87(I/O,_L29P_Y)* 88(I/O,_L28N_Y)* 89(I/O,_L28P_Y)* 93(I/O,_L27N_Y)* 94(I/O,_VREF_4,_L27P_Y)* 95(I/O)* 182(GCK2,_I)*

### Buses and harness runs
bus ADDR[2..0] = port ADDR[2..0]
bus BOARD_ADDR[7..0] = port BOARD_ADDR[7..0]
bus DATA[7..0] = port DATA[7..0]
bus ENABLE[7..0] = port ENABLE[7..0]
bus GREEN[4..0] = port GREEN[4..0]
bus JUMPERS[7..0] = port JUMPERS[7..0]
bus LED[7..0] = port LED[7..0]
bus RED[4..0] = port RED[4..0]
bus ROWA[6..0] = port ROWA[6..0]
bus ROWB[6..0] = port ROWB[6..0]
bus ROWC[6..0] = port ROWC[6..0]
bus ROWD[6..0] = port ROWD[6..0]
bus ROWE[6..0] = port ROWE[6..0]
bus ROWF[6..0] = port ROWF[6..0]
bus ROWG[6..0] = port ROWG[6..0]
bus ROWH[6..0] = port ROWH[6..0]

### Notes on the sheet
- WARNING : THIS IS AN AUTOGENERATED FILE

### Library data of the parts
U1 = XC2S300E-6PQ208C: Spartan-IIE 1.8V FPGA, 208-Pin PQFP, Standard Performance, Commercial Grade; Package Information: Latest Revision: ver1.1, Oct-2002; Code - JEDEC: MS-029-FA-1

## Sheet Power.SchDoc: Board-On-Chip Power Supply
size A4; Organization: Altium Limited; Address1: L3, 12a Rodborough Rd; Address2: Frenchs Forest; Address3: NSW; Address4: Australia 2086; DocumentNumber: 3; Revision: 1.05; SheetNumber: 3; SheetTotal: 7
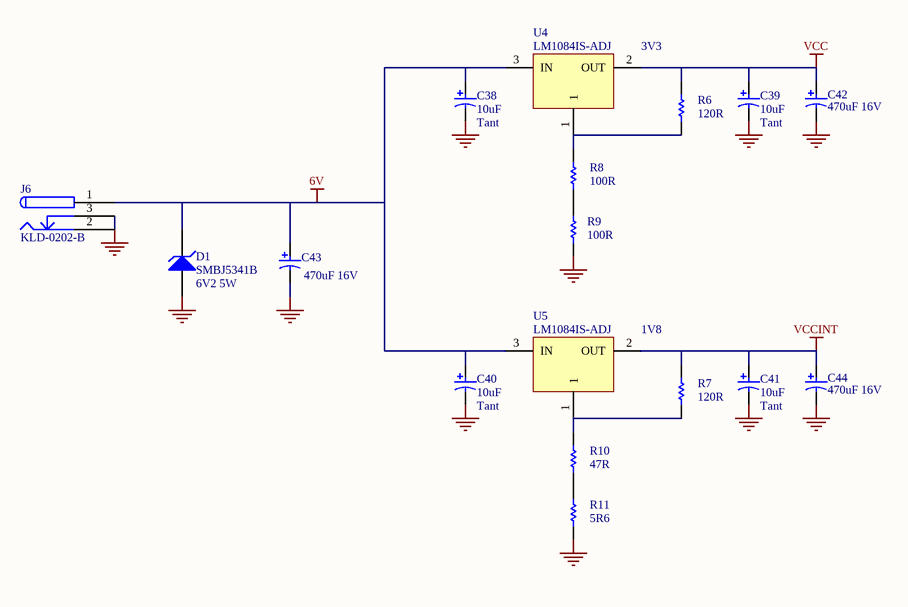
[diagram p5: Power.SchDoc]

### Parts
C38  10uF  Capacitor Type: Tant  [MCCT-B]
C39  10uF  Capacitor Type: Tant  [MCCT-B]
C40  10uF  Capacitor Type: Tant  [MCCT-B]
C41  10uF  Capacitor Type: Tant  [MCCT-B]
C42  470uF 16V  [RB8/3.5]
C43  470uF 16V  [RB8/3.5]
C44  470uF 16V  [RB8/3.5]
D1  SMBJ5341B  Part Description: 6V2 5W  [DO214]
J6  KLD-0202-B  [KLD-0202]
R6  120R  [CC2012-0805]
R7  120R  [CC2012-0805]
R8  100R  [CC2012-0805]
R9  100R  [CC2012-0805]
R10  47R  [CC2012-0805]
R11  5R6  [CC2012-0805]
U4  LM1084IS-ADJ  [TO-263]
U5  LM1084IS-ADJ  [TO-263]

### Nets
6V: C38.1 C40.1 C43.1 D1.2(K) J6.1 J6.1A J6.1B U4.3(IN) U5.3(IN)
GND: C38.2 C39.2 C40.2 C41.2 C42.2 C43.2 C44.2 D1.1(A) J6.2 J6.2A J6.2B J6.3 J6.3A J6.3B R9.1 R11.2
VCC: C39.1 C42.1 R6.1 U4.2(OUT)  [project net VCCO]
VCCINT: C41.1 C44.1 R7.1 U5.2(OUT)
NetR6_2: R6.2 R8.1 U4.1
NetR7_2: R7.2 R10.1 U5.1
NetR8_2: R8.2 R9.2
NetR10_2: R10.2 R11.1

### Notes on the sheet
- 3V3
- 1V8

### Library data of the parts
C38-C44 = CAP_POLAR: Polar Capacitor; Fitted: True
D1 = BZG03C13: Zener Diode, 6.2V, 5W; Manufacturer: Microsemi; Fitted: True
J6 = KLD-0202-B: Low Voltage Power Supply Connector; Manufacturer: Kycon; Fitted: True
R6-R11 = RES: Resistor; Fitted: True
U4 U5 = LM1084IS-ADJ: 5A Low Dropout Possitive Regulators; Fitted: True

## Sheet LED_DIPSWITCH.SchDoc: Board-On-Chip LEDs and DIP Switch
size A4; Organization: Altium Limited; Address1: L3, 12a Rodborough Rd; Address2: Frenchs Forest; Address3: NSW; Address4: Australia 2086; DocumentNumber: 5; Revision: 1.05; SheetNumber: 5; SheetTotal: 7
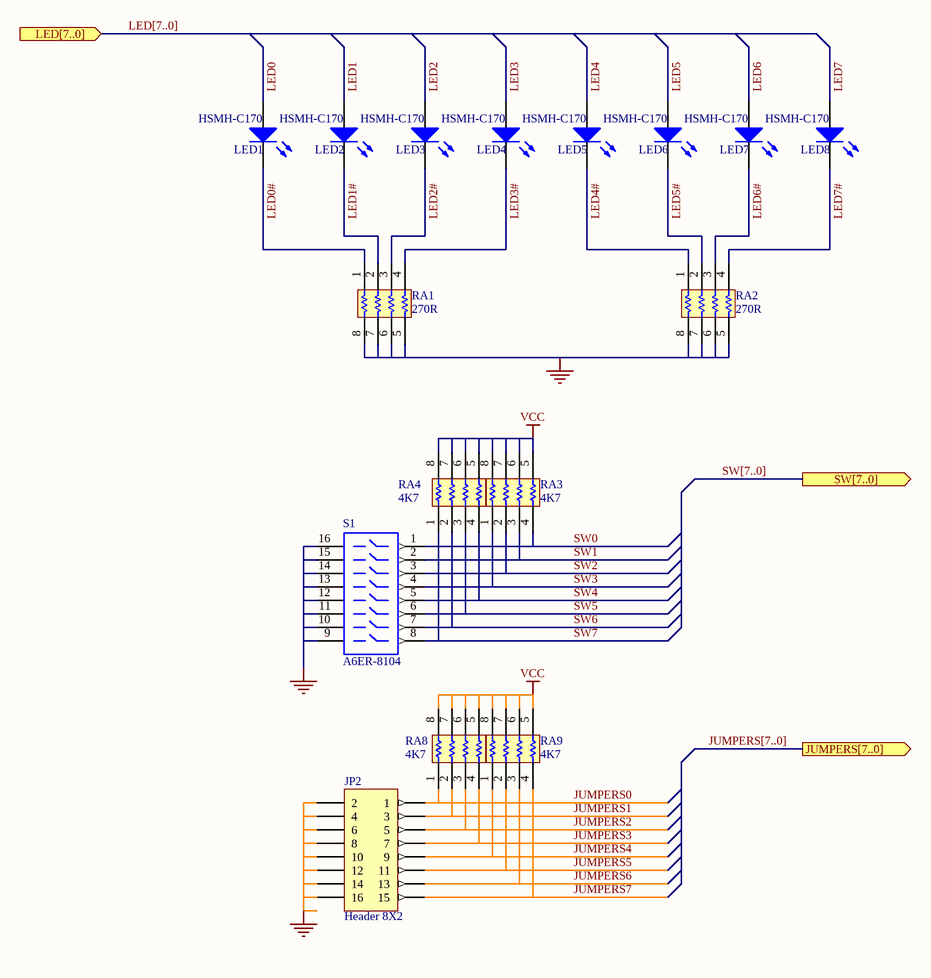
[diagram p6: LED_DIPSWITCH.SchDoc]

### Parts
JP2  Header 8X2  [HDR2X8]
LED1  HSMH-C170  [SMD _LED]
LED2  HSMH-C170  [SMD _LED]
LED3  HSMH-C170  [SMD _LED]
LED4  HSMH-C170  [SMD _LED]
LED5  HSMH-C170  [SMD _LED]
LED6  HSMH-C170  [SMD _LED]
LED7  HSMH-C170  [SMD _LED]
LED8  HSMH-C170  [SMD _LED]
RA1  270R  [MNR34]
RA2  270R  [MNR34]
RA3  4K7  [MNR34]
RA4  4K7  [MNR34]
RA8  4K7  [MNR34]
RA9  4K7  [MNR34]
S1  A6ER-8104  [DIP-16-KEY]

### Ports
JUMPERS[7..0] (out), LED[7..0] (in), SW[7..0] (out)

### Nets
GND: JP2.2 JP2.4 JP2.6 JP2.8 JP2.10 JP2.12 JP2.14 JP2.16 RA1.5 RA1.6 RA1.7 RA1.8 RA2.5 RA2.6 RA2.7 RA2.8 S1.9 S1.10 S1.11 S1.12 S1.13 S1.14 S1.15 S1.16
VCC: RA3.5 RA3.6 RA3.7 RA3.8 RA4.5 RA4.6 RA4.7 RA4.8 RA8.5 RA8.6 RA8.7 RA8.8 RA9.5 RA9.6 RA9.7 RA9.8  [project net VCCO]
JUMPERS0: JP2.1 RA8.1
JUMPERS1: JP2.3 RA8.2
JUMPERS2: JP2.5 RA8.3
JUMPERS3: JP2.7 RA8.4
JUMPERS4: JP2.9 RA9.1
JUMPERS5: JP2.11 RA9.2
JUMPERS6: JP2.13 RA9.3
JUMPERS7: JP2.15 RA9.4
LED0: LED1.1(A)
LED0#: LED1.2(K) RA1.1
LED1: LED2.1(A)
LED1#: LED2.2(K) RA1.2
LED2: LED3.1(A)
LED2#: LED3.2(K) RA1.3
LED3: LED4.1(A)
LED3#: LED4.2(K) RA1.4
LED4: LED5.1(A)
LED4#: LED5.2(K) RA2.1
LED5: LED6.1(A)
LED5#: LED6.2(K) RA2.2
LED6: LED7.1(A)
LED6#: LED7.2(K) RA2.3
LED7: LED8.1(A)
LED7#: LED8.2(K) RA2.4
SW0: RA3.4 S1.1
SW1: RA3.3 S1.2
SW2: RA3.2 S1.3
SW3: RA3.1 S1.4
SW4: RA4.4 S1.5
SW5: RA4.3 S1.6
SW6: RA4.2 S1.7
SW7: RA4.1 S1.8

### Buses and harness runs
bus JUMPERS[7..0] = port JUMPERS[7..0]
bus LED[7..0] = port LED[7..0]
bus SW[7..0] = port SW[7..0]

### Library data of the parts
JP2 = Header 8X2: Header, 8-Pin, Dual row; Manufacturer: Generic Components; Class I: Connector
LED1-LED8 = HSMX-C670: Typical RED GaAs SMD LED Agilent make; Manufacturer: Generic Components; Class I: Optoelectronic; Fitted: True
RA1-RA4 RA8 RA9 = MNR34: 3216x4 Resistor Array; Fitted: True
S1 = A6ER-8104: DIP Switch Side actuator long liver Piano Key; Manufacturer: Generic Components; Fitted: True

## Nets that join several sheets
6V: LedMatrixDisplay (16 pins), DIGITS/DG7 (J1_DG7.12 J1_DG7.13 J1_DG7.14), DIGITS/DG6 (J1_DG6.12 J1_DG6.13 J1_DG6.14), DIGITS/DG5 (J1_DG5.12 J1_DG5.13 J1_DG5.14), DIGITS/DG4 (J1_DG4.12 J1_DG4.13 J1_DG4.14), DIGITS/DG3 (J1_DG3.12 J1_DG3.13 J1_DG3.14), DIGITS/DG2 (J1_DG2.12 J1_DG2.13 J1_DG2.14), DIGITS/DG1 (J1_DG1.12 J1_DG1.13 J1_DG1.14), DIGITS/DG8 (J1_DG8.12 J1_DG8.13 J1_DG8.14), Power (9 pins)
GND: LedMatrixDisplay (17 pins), DIGITS/DG7 (J2_DG7.12 J2_DG7.13 J2_DG7.14), DIGITS/DG6 (J2_DG6.12 J2_DG6.13 J2_DG6.14), DIGITS/DG5 (J2_DG5.12 J2_DG5.13 J2_DG5.14), DIGITS/DG4 (J2_DG4.12 J2_DG4.13 J2_DG4.14), DIGITS/DG3 (J2_DG3.12 J2_DG3.13 J2_DG3.14), DIGITS/DG2 (J2_DG2.12 J2_DG2.13 J2_DG2.14), DIGITS/DG1 (J2_DG1.12 J2_DG1.13 J2_DG1.14), DIGITS/DG8 (J2_DG8.12 J2_DG8.13 J2_DG8.14), FPGA_U1_Manual (37 pins), FPGA_U1_Auto (26 pins), Power (16 pins), LED_DIPSWITCH (24 pins)
VCCINT: FPGA_U1_Manual (14 pins), FPGA_U1_Auto (12 pins), Power (C41.1 C44.1 R7.1 U5.2)
VCCO: LedMatrixDisplay (C37.1 U3.1 U3.4), DIGITS/DG7 (J1_DG7.1 J1_DG7.2 J1_DG7.3), DIGITS/DG6 (J1_DG6.1 J1_DG6.2 J1_DG6.3), DIGITS/DG5 (J1_DG5.1 J1_DG5.2 J1_DG5.3), DIGITS/DG4 (J1_DG4.1 J1_DG4.2 J1_DG4.3), DIGITS/DG3 (J1_DG3.1 J1_DG3.2 J1_DG3.3), DIGITS/DG2 (J1_DG2.1 J1_DG2.2 J1_DG2.3), DIGITS/DG1 (J1_DG1.1 J1_DG1.2 J1_DG1.3), DIGITS/DG8 (J1_DG8.1 J1_DG8.2 J1_DG8.3), FPGA_U1_Manual (28 pins), FPGA_U1_Auto (16 pins), Power (C39.1 C42.1 R6.1 U4.2), LED_DIPSWITCH (16 pins)
ADDR0: LedMatrixDisplay (RA7.5), FPGA_U1_Auto (U1.110)
ADDR1: LedMatrixDisplay (RA7.6), FPGA_U1_Auto (U1.109)
ADDR2: LedMatrixDisplay (RA7.7), FPGA_U1_Auto (U1.97)
CCLK: FPGA_U1_Manual (U2.3), FPGA_U1_Auto (U1.155)
CLK_MHZ40: LedMatrixDisplay (R5.2), FPGA_U1_Auto (U1.185)
DATA0: LedMatrixDisplay (RA5.5), FPGA_U1_Auto (U1.99)
DATA1: LedMatrixDisplay (RA5.6), FPGA_U1_Auto (U1.100)
DATA2: LedMatrixDisplay (RA5.7), FPGA_U1_Auto (U1.101)
DATA3: LedMatrixDisplay (RA5.8), FPGA_U1_Auto (U1.102)
DATA4: LedMatrixDisplay (RA6.5), FPGA_U1_Auto (U1.114)
DATA5: LedMatrixDisplay (RA6.6), FPGA_U1_Auto (U1.113)
DATA6: LedMatrixDisplay (RA6.7), FPGA_U1_Auto (U1.112)
DATA7: LedMatrixDisplay (RA6.8), FPGA_U1_Auto (U1.111)
DIN: FPGA_U1_Manual (U2.1), FPGA_U1_Auto (U1.153)
DONE: FPGA_U1_Manual (R4.2 U2.10), FPGA_U1_Auto (U1.104)
ENABLE0: DIGITS/DG1 (J1_DG1.11), FPGA_U1_Auto (U1.132)
ENABLE1: DIGITS/DG2 (J1_DG2.11), FPGA_U1_Auto (U1.150)
ENABLE2: DIGITS/DG3 (J1_DG3.11), FPGA_U1_Auto (U1.168)
ENABLE3: DIGITS/DG4 (J1_DG4.11), FPGA_U1_Auto (U1.68)
ENABLE4: DIGITS/DG5 (J1_DG5.11), FPGA_U1_Auto (U1.193)
ENABLE5: DIGITS/DG6 (J1_DG6.11), FPGA_U1_Auto (U1.204)
ENABLE6: DIGITS/DG7 (J1_DG7.11), FPGA_U1_Auto (U1.8)
ENABLE7: DIGITS/DG8 (J1_DG8.11), FPGA_U1_Auto (U1.22)
FPGA_TDO-TDI: FPGA_U1_Manual (U2.4), FPGA_U1_Auto (U1.157)
GREEN0: DIGITS/DG7 (J2_DG7.1), DIGITS/DG6 (J2_DG6.1), DIGITS/DG5 (J2_DG5.1), DIGITS/DG4 (J2_DG4.1), DIGITS/DG3 (J2_DG3.1), DIGITS/DG2 (J2_DG2.1), DIGITS/DG1 (J2_DG1.1), DIGITS/DG8 (J2_DG8.1), FPGA_U1_Auto (U1.167)
GREEN1: DIGITS/DG7 (J2_DG7.2), DIGITS/DG6 (J2_DG6.2), DIGITS/DG5 (J2_DG5.2), DIGITS/DG4 (J2_DG4.2), DIGITS/DG3 (J2_DG3.2), DIGITS/DG2 (J2_DG2.2), DIGITS/DG1 (J2_DG1.2), DIGITS/DG8 (J2_DG8.2), FPGA_U1_Auto (U1.96)
GREEN2: DIGITS/DG7 (J2_DG7.3), DIGITS/DG6 (J2_DG6.3), DIGITS/DG5 (J2_DG5.3), DIGITS/DG4 (J2_DG4.3), DIGITS/DG3 (J2_DG3.3), DIGITS/DG2 (J2_DG2.3), DIGITS/DG1 (J2_DG1.3), DIGITS/DG8 (J2_DG8.3), FPGA_U1_Auto (U1.135)
GREEN3: DIGITS/DG7 (J2_DG7.4), DIGITS/DG6 (J2_DG6.4), DIGITS/DG5 (J2_DG5.4), DIGITS/DG4 (J2_DG4.4), DIGITS/DG3 (J2_DG3.4), DIGITS/DG2 (J2_DG2.4), DIGITS/DG1 (J2_DG1.4), DIGITS/DG8 (J2_DG8.4), FPGA_U1_Auto (U1.45)
GREEN4: DIGITS/DG7 (J2_DG7.5), DIGITS/DG6 (J2_DG6.5), DIGITS/DG5 (J2_DG5.5), DIGITS/DG4 (J2_DG4.5), DIGITS/DG3 (J2_DG3.5), DIGITS/DG2 (J2_DG2.5), DIGITS/DG1 (J2_DG1.5), DIGITS/DG8 (J2_DG8.5), FPGA_U1_Auto (U1.17)
INIT: FPGA_U1_Manual (R3.2 U2.8), FPGA_U1_Auto (U1.107)
JUMPERS0: FPGA_U1_Auto (U1.33), LED_DIPSWITCH (JP2.1 RA8.1)
JUMPERS1: FPGA_U1_Auto (U1.31), LED_DIPSWITCH (JP2.3 RA8.2)
JUMPERS2: FPGA_U1_Auto (U1.30), LED_DIPSWITCH (JP2.5 RA8.3)
JUMPERS3: FPGA_U1_Auto (U1.21), LED_DIPSWITCH (JP2.7 RA8.4)
JUMPERS4: FPGA_U1_Auto (U1.29), LED_DIPSWITCH (JP2.9 RA9.1)
JUMPERS5: FPGA_U1_Auto (U1.27), LED_DIPSWITCH (JP2.11 RA9.2)
JUMPERS6: FPGA_U1_Auto (U1.24), LED_DIPSWITCH (JP2.13 RA9.3)
JUMPERS7: FPGA_U1_Auto (U1.23), LED_DIPSWITCH (JP2.15 RA9.4)
LED0: FPGA_U1_Auto (U1.35), LED_DIPSWITCH (LED1.1)
LED1: FPGA_U1_Auto (U1.34), LED_DIPSWITCH (LED2.1)
LED2: FPGA_U1_Auto (U1.36), LED_DIPSWITCH (LED3.1)
LED3: FPGA_U1_Auto (U1.40), LED_DIPSWITCH (LED4.1)
LED4: FPGA_U1_Auto (U1.41), LED_DIPSWITCH (LED5.1)
LED5: FPGA_U1_Auto (U1.42), LED_DIPSWITCH (LED6.1)
LED6: FPGA_U1_Auto (U1.43), LED_DIPSWITCH (LED7.1)
LED7: FPGA_U1_Auto (U1.44), LED_DIPSWITCH (LED8.1)
PROGRAM: FPGA_U1_Manual (R2.2 U2.7), FPGA_U1_Auto (U1.106)
RED0: DIGITS/DG7 (J2_DG7.7), DIGITS/DG6 (J2_DG6.7), DIGITS/DG5 (J2_DG5.7), DIGITS/DG4 (J2_DG4.7), DIGITS/DG3 (J2_DG3.7), DIGITS/DG2 (J2_DG2.7), DIGITS/DG1 (J2_DG1.7), DIGITS/DG8 (J2_DG8.7), FPGA_U1_Auto (U1.57)
RED1: DIGITS/DG7 (J2_DG7.8), DIGITS/DG6 (J2_DG6.8), DIGITS/DG5 (J2_DG5.8), DIGITS/DG4 (J2_DG4.8), DIGITS/DG3 (J2_DG3.8), DIGITS/DG2 (J2_DG2.8), DIGITS/DG1 (J2_DG1.8), DIGITS/DG8 (J2_DG8.8), FPGA_U1_Auto (U1.59)
RED2: DIGITS/DG7 (J2_DG7.9), DIGITS/DG6 (J2_DG6.9), DIGITS/DG5 (J2_DG5.9), DIGITS/DG4 (J2_DG4.9), DIGITS/DG3 (J2_DG3.9), DIGITS/DG2 (J2_DG2.9), DIGITS/DG1 (J2_DG1.9), DIGITS/DG8 (J2_DG8.9), FPGA_U1_Auto (U1.60)
RED3: DIGITS/DG7 (J2_DG7.10), DIGITS/DG6 (J2_DG6.10), DIGITS/DG5 (J2_DG5.10), DIGITS/DG4 (J2_DG4.10), DIGITS/DG3 (J2_DG3.10), DIGITS/DG2 (J2_DG2.10), DIGITS/DG1 (J2_DG1.10), DIGITS/DG8 (J2_DG8.10), FPGA_U1_Auto (U1.61)
RED4: DIGITS/DG7 (J2_DG7.11), DIGITS/DG6 (J2_DG6.11), DIGITS/DG5 (J2_DG5.11), DIGITS/DG4 (J2_DG4.11), DIGITS/DG3 (J2_DG3.11), DIGITS/DG2 (J2_DG2.11), DIGITS/DG1 (J2_DG1.11), DIGITS/DG8 (J2_DG8.11), FPGA_U1_Auto (U1.63)
ROWA0: DIGITS/DG1 (J1_DG1.4), FPGA_U1_Auto (U1.115)
ROWA1: DIGITS/DG1 (J1_DG1.5), FPGA_U1_Auto (U1.121)
ROWA2: DIGITS/DG1 (J1_DG1.6), FPGA_U1_Auto (U1.122)
ROWA3: DIGITS/DG1 (J1_DG1.7), FPGA_U1_Auto (U1.123)
ROWA4: DIGITS/DG1 (J1_DG1.8), FPGA_U1_Auto (U1.125)
ROWA5: DIGITS/DG1 (J1_DG1.9), FPGA_U1_Auto (U1.127)
ROWA6: DIGITS/DG1 (J1_DG1.10), FPGA_U1_Auto (U1.129)
ROWB0: DIGITS/DG2 (J1_DG2.4), FPGA_U1_Auto (U1.136)
ROWB1: DIGITS/DG2 (J1_DG2.5), FPGA_U1_Auto (U1.140)
ROWB2: DIGITS/DG2 (J1_DG2.6), FPGA_U1_Auto (U1.141)
ROWB3: DIGITS/DG2 (J1_DG2.7), FPGA_U1_Auto (U1.146)
ROWB4: DIGITS/DG2 (J1_DG2.8), FPGA_U1_Auto (U1.147)
ROWB5: DIGITS/DG2 (J1_DG2.9), FPGA_U1_Auto (U1.148)
ROWB6: DIGITS/DG2 (J1_DG2.10), FPGA_U1_Auto (U1.149)
ROWC0: DIGITS/DG4 (J1_DG4.4), FPGA_U1_Auto (U1.169)
ROWC1: DIGITS/DG4 (J1_DG4.5), FPGA_U1_Auto (U1.173)
ROWC2: DIGITS/DG4 (J1_DG4.6), FPGA_U1_Auto (U1.174)
ROWC3: DIGITS/DG4 (J1_DG4.7), FPGA_U1_Auto (U1.175)
ROWC4: DIGITS/DG4 (J1_DG4.8), FPGA_U1_Auto (U1.176)
ROWC5: DIGITS/DG4 (J1_DG4.9), FPGA_U1_Auto (U1.178)
ROWC6: DIGITS/DG4 (J1_DG4.10), FPGA_U1_Auto (U1.179)
ROWD0: DIGITS/DG6 (J1_DG6.4), FPGA_U1_Auto (U1.194)
ROWD1: DIGITS/DG6 (J1_DG6.5), FPGA_U1_Auto (U1.198)
ROWD2: DIGITS/DG6 (J1_DG6.6), FPGA_U1_Auto (U1.199)
ROWD3: DIGITS/DG6 (J1_DG6.7), FPGA_U1_Auto (U1.200)
ROWD4: DIGITS/DG6 (J1_DG6.8), FPGA_U1_Auto (U1.201)
ROWD5: DIGITS/DG6 (J1_DG6.9), FPGA_U1_Auto (U1.202)
ROWD6: DIGITS/DG6 (J1_DG6.10), FPGA_U1_Auto (U1.203)
ROWE0: DIGITS/DG3 (J1_DG3.4), FPGA_U1_Auto (U1.151)
ROWE1: DIGITS/DG3 (J1_DG3.5), FPGA_U1_Auto (U1.152)
ROWE2: DIGITS/DG3 (J1_DG3.6), FPGA_U1_Auto (U1.162)
ROWE3: DIGITS/DG3 (J1_DG3.7), FPGA_U1_Auto (U1.163)
ROWE4: DIGITS/DG3 (J1_DG3.8), FPGA_U1_Auto (U1.164)
ROWE5: DIGITS/DG3 (J1_DG3.9), FPGA_U1_Auto (U1.165)
ROWE6: DIGITS/DG3 (J1_DG3.10), FPGA_U1_Auto (U1.166)
ROWF0: DIGITS/DG8 (J1_DG8.4), FPGA_U1_Auto (U1.9)
ROWF1: DIGITS/DG8 (J1_DG8.5), FPGA_U1_Auto (U1.10)
ROWF2: DIGITS/DG8 (J1_DG8.6), FPGA_U1_Auto (U1.11)
ROWF3: DIGITS/DG8 (J1_DG8.7), FPGA_U1_Auto (U1.15)
ROWF4: DIGITS/DG8 (J1_DG8.8), FPGA_U1_Auto (U1.16)
ROWF5: DIGITS/DG8 (J1_DG8.9), FPGA_U1_Auto (U1.18)
ROWF6: DIGITS/DG8 (J1_DG8.10), FPGA_U1_Auto (U1.20)
ROWG0: DIGITS/DG7 (J1_DG7.4), FPGA_U1_Auto (U1.205)
ROWG1: DIGITS/DG7 (J1_DG7.5), FPGA_U1_Auto (U1.206)
ROWG2: DIGITS/DG7 (J1_DG7.6), FPGA_U1_Auto (U1.4)
ROWG3: DIGITS/DG7 (J1_DG7.7), FPGA_U1_Auto (U1.3)
ROWG4: DIGITS/DG7 (J1_DG7.8), FPGA_U1_Auto (U1.5)
ROWG5: DIGITS/DG7 (J1_DG7.9), FPGA_U1_Auto (U1.6)
ROWG6: DIGITS/DG7 (J1_DG7.10), FPGA_U1_Auto (U1.7)
ROWH0: DIGITS/DG5 (J1_DG5.4), FPGA_U1_Auto (U1.180)
ROWH1: DIGITS/DG5 (J1_DG5.5), FPGA_U1_Auto (U1.181)
ROWH2: DIGITS/DG5 (J1_DG5.6), FPGA_U1_Auto (U1.187)
ROWH3: DIGITS/DG5 (J1_DG5.7), FPGA_U1_Auto (U1.188)
ROWH4: DIGITS/DG5 (J1_DG5.8), FPGA_U1_Auto (U1.189)
ROWH5: DIGITS/DG5 (J1_DG5.9), FPGA_U1_Auto (U1.191)
ROWH6: DIGITS/DG5 (J1_DG5.10), FPGA_U1_Auto (U1.192)
SPARTAN_M0: FPGA_U1_Manual (JP1.1 R1.2), FPGA_U1_Auto (U1.52)
SW0: FPGA_U1_Auto (U1.46), LED_DIPSWITCH (RA3.4 S1.1)
SW1: FPGA_U1_Auto (U1.47), LED_DIPSWITCH (RA3.3 S1.2)
SW2: FPGA_U1_Auto (U1.48), LED_DIPSWITCH (RA3.2 S1.3)
SW3: FPGA_U1_Auto (U1.49), LED_DIPSWITCH (RA3.1 S1.4)
SW4: FPGA_U1_Auto (U1.62), LED_DIPSWITCH (RA4.4 S1.5)
SW5: FPGA_U1_Auto (U1.58), LED_DIPSWITCH (RA4.3 S1.6)
SW6: FPGA_U1_Auto (U1.56), LED_DIPSWITCH (RA4.2 S1.7)
SW7: FPGA_U1_Auto (U1.55), LED_DIPSWITCH (RA4.1 S1.8)
TCK_HARD: LedMatrixDisplay (J5.3), FPGA_U1_Manual (U2.6), FPGA_U1_Auto (U1.207)
TCK_SOFT: LedMatrixDisplay (J5.7), FPGA_U1_Auto (U1.139)
TDI_HARD: LedMatrixDisplay (J5.1), FPGA_U1_Auto (U1.159)
TDI_SOFT: LedMatrixDisplay (J5.5), FPGA_U1_Auto (U1.138)
TDO_HARD: LedMatrixDisplay (J5.2), FPGA_U1_Manual (U2.17)
TDO_SOFT: LedMatrixDisplay (J5.6), FPGA_U1_Auto (U1.133)
TMS_HARD: LedMatrixDisplay (J5.4), FPGA_U1_Manual (U2.5), FPGA_U1_Auto (U1.2)
TMS_SOFT: LedMatrixDisplay (J5.8), FPGA_U1_Auto (U1.134)
WR: LedMatrixDisplay (RA7.8), FPGA_U1_Auto (U1.98)
WR_REG: LedMatrixDisplay (R12.1), FPGA_U1_Auto (U1.86)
